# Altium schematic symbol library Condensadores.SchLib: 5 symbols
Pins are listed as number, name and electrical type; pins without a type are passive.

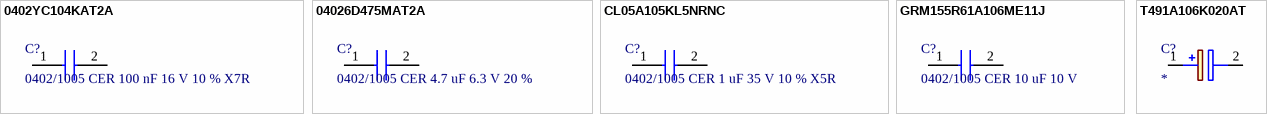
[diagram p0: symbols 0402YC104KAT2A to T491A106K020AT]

## 0402YC104KAT2A
designator C?, comment 0402/1005 CER 100 nF 16 V 10 % X7R
0402/1005 CER nF 100 16 V 10 % X7R; Manufacturer_Name: Kyocera AVX; Manufacturer_Part_Number: 0402YC104KAT2A; Dielectric Material: Ceramic; Material: 4241ConductorMaterial; Tolerance: 10%; Value: 100nF; Voltage Rating: 16V
footprint CAPC1005X56N
pins: 1, 2

## 04026D475MAT2A
designator C?, comment 0402/1005 CER 4.7 uF 6.3 V 20 %
0402/1005 CER uF 4.7 6.3 V 20 %; Manufacturer_Name: Kyocera AVX; Manufacturer_Part_Number: 04026D475MAT2A; Material: 4241ConductorMaterial; Voltage Rating (DC): 6.3V
footprint CAPC1005X56N
pins: 1, 2

## CL05A105KL5NRNC
designator C?, comment 0402/1005 CER 1 uF 35 V 10 % X5R
0402/1005 CER uF 1 35 V 10 % X5R; Manufacturer_Name: SAMSUNG; Manufacturer_Part_Number: CL05A105KL5NRNC; Material: 4241ConductorMaterial; Value: 1uF; Voltage Rating: 35V; Tolerance: 10%
footprint CAPC1005X65N
pins: 1, 2

## GRM155R61A106ME11J
designator C?, comment 0402/1005 CER 10 uF 10 V
0402/1005 CER uF 10 10 V; Manufacturer_Name: Murata Electronics; Manufacturer_Part_Number: GRM155R61A106ME11J; Manufacturer: Murata; Material: 4241ConductorMaterial; Value: 10uF; Dielectric: 1537DielectricType; Tolerance: 20%; Voltage Rating: 10V
footprint GRM15x
pins: 1, 2

## T491A106K020AT
designator C?
Capacitor Polarised; Manufacturer_Name: KEMET; Manufacturer_Part_Number: T491A106K020AT; Description: T491
footprint T491A
pins: 1 +, 2 -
